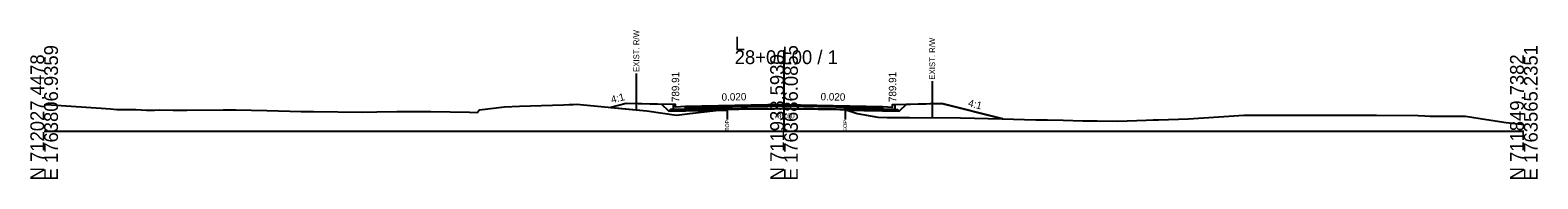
# Model space of a CAD drawing. Extents: x -26 to 5303, y -10 to 9578.
# Drawn here: x 997.2 to 1302.8, y 7990.3 to 8020.5 of the extents above; entities that cross this region are included whole.
import ezdxf

# ---------------------------------------------------------------- set-up
doc = ezdxf.new("R2010")
doc.units = 0
for name, color, linetype in [('Default', 7, 'Continuous'), ('Exist CMT Pavement', 7, 'Continuous'), ('Exist Cross Section Cell', 7, 'Continuous'), ('Exist XS Ground Line', 7, 'Continuous'), ('Old_Level_10', 7, 'Continuous'), ('Old_Level_3', 7, 'Continuous'), ('Prop CMT Conc Surface', 7, 'Continuous'), ('Prop CMT Concrete Structures', 7, 'Continuous'), ('Prop CMT Pvmt Course 1', 7, 'Continuous'), ('Prop CMT Pvmt Course 1 CG', 7, 'Continuous'), ('Prop CMT Pvmt Course 2', 7, 'Continuous'), ('Prop CMT Pvmt Course 3', 7, 'Continuous'), ('Prop CMT Pvmt Surface', 7, 'Continuous'), ('Prop CMT Slope Grass', 7, 'Continuous'), ('Prop CMT Subgrade Earthwork', 7, 'Continuous'), ('Prop XS Earthwork Shape', 7, 'Continuous'), ('Prop XS Hydro Elevations', 7, 'Continuous'), ('Prop XS SE Text', 7, 'Continuous'), ('Prop XS Side Slope Text', 7, 'Continuous'), ('Prop XS Wedging', 7, 'Continuous')]:
    doc.layers.add(name, color=color, linetype=linetype)

msp = doc.modelspace()

# ---------------------------------------------------------------- linework, layer by layer
at = {"layer": 'Exist CMT Pavement'}
msp.add_lwpolyline([(1138.45, 8004.45), (1138.82, 8004.47), (1139.26, 8004.47), (1139.57, 8004.48), (1140.49, 8004.5), (1140.83, 8004.5), (1141.29, 8004.51), (1142.62, 8004.53), (1143.59, 8004.53), (1144.41, 8004.54), (1145.51, 8004.55), (1146.19, 8004.55), (1146.69, 8004.56), (1147.98, 8004.57), (1150.16, 8004.6), (1150.7, 8004.61), (1151.01, 8004.59), (1152.9, 8004.54), (1153.96, 8004.53), (1156, 8004.51), (1156.92, 8004.49), (1158.18, 8004.48), (1159.1, 8004.47), (1160.5, 8004.45), (1161.29, 8004.43), (1161.91, 8004.41), (1162.39, 8004.39)], dxfattribs=at)
at = {"layer": 'Exist Cross Section Cell'}
for p, q in [((1150, 8000), (1150, 8016.43)), ((1000, 8000), (1150, 8000)), ((1150, 8000), (1300, 8000))]:
    msp.add_line(p, q, dxfattribs=at)
at = {"layer": 'Exist XS Ground Line'}
msp.add_lwpolyline([(1000, 8005.43), (1001.45, 8005.38), (1011.56, 8004.68), (1013.42, 8004.52), (1014.73, 8004.39), (1017.08, 8004.4), (1018.58, 8004.4), (1020.74, 8004.3), (1022.39, 8004.3), (1023.47, 8004.31), (1026.15, 8004.3), (1028.91, 8004.3), (1036.31, 8004.33), (1037.84, 8004.33), (1038.86, 8004.34), (1045.13, 8004.18), (1052.11, 8003.98), (1053.17, 8003.99), (1054.62, 8003.97), (1064.52, 8003.88), (1067.48, 8003.91), (1071.51, 8003.97), (1078.41, 8003.97), (1086.26, 8003.89), (1087.76, 8003.82), (1088.26, 8004.32), (1093.36, 8004.93), (1096.35, 8005.05), (1105.26, 8005.33), (1106.44, 8005.39), (1107.24, 8005.43), (1107.9, 8005.48), (1122.18, 8004.12), (1128.22, 8003.26), (1130.88, 8003.62), (1138.45, 8004.45), (1138.82, 8004.47), (1139.26, 8004.47), (1139.57, 8004.48), (1140.49, 8004.5), (1140.83, 8004.5), (1141.29, 8004.51), (1143.59, 8004.53), (1144.41, 8004.54), (1145.51, 8004.55), (1146.19, 8004.55), (1146.69, 8004.56), (1150.16, 8004.6), (1150.7, 8004.61), (1151.01, 8004.59), (1151.56, 8004.56), (1152.9, 8004.54), (1153.35, 8004.54), (1153.96, 8004.53), (1155.13, 8004.52), (1156, 8004.51), (1156.92, 8004.49), (1158.18, 8004.48), (1158.71, 8004.48), (1159.1, 8004.47), (1160.5, 8004.45), (1161.29, 8004.43), (1161.91, 8004.41), (1162.39, 8004.39), (1164.86, 8003.61), (1169, 8002.85), (1170.94, 8002.75), (1175.45, 8002.81), (1185.81, 8002.72), (1194.22, 8002.51), (1201.07, 8002.33), (1203.41, 8002.3), (1206.58, 8002.23), (1210.56, 8002.1), (1213.49, 8002.1), (1217.71, 8002.04), (1223.46, 8002.22), (1224.87, 8002.28), (1225.9, 8002.32), (1232.02, 8002.51), (1239.16, 8002.96), (1243.22, 8003.25), (1244.1, 8003.25), (1245.22, 8003.25), (1270.16, 8003.22), (1278.57, 8003.16), (1279.91, 8003.13), (1281.03, 8003.05), (1288.19, 8003.02), (1292.46, 8002.4), (1296.4, 8001.74), (1299.44, 8001.4), (1300, 8001.34)], dxfattribs=at)
at = {"layer": 'Old_Level_10'}
for p, q in [((1120.05, 8011.72), (1120.05, 8004.32)), ((1180.05, 8010.17), (1180.05, 8002.77)), ((1138.45, 8004.45), (1138.45, 8002.4)), ((1162.39, 8004.39), (1162.39, 8002.34))]:
    msp.add_line(p, q, dxfattribs=at)
at = {"layer": 'Prop CMT Conc Surface'}
for points in [[(1128, 8004.91), (1128, 8005.41), (1127.5, 8005.41)], [(1130, 8005.03), (1128, 8004.91)], [(1170, 8005.03), (1172, 8004.91)], [(1172, 8004.91), (1172, 8005.41), (1172.5, 8005.41)]]:
    msp.add_lwpolyline(points, dxfattribs=at)
at = {"layer": 'Prop CMT Concrete Structures'}
for points in [[(1130, 8005.03), (1128, 8004.91), (1128, 8005.41), (1127.5, 8005.41)], [(1127.5, 8005.41), (1127.5, 8004.4), (1130, 8004.45)], [(1130, 8004.45), (1130, 8005.03)], [(1170, 8005.03), (1172, 8004.91), (1172, 8005.41), (1172.5, 8005.41)], [(1172.5, 8005.41), (1172.5, 8004.4), (1170, 8004.45)], [(1170, 8004.45), (1170, 8005.03)]]:
    msp.add_lwpolyline(points, dxfattribs=at)
at = {"layer": 'Prop CMT Pvmt Course 1'}
for points in [[(1150, 8005.43), (1130, 8005.03)], [(1130, 8005.03), (1130, 8004.78)], [(1130, 8004.78), (1138.45, 8004.95)], [(1138.45, 8004.95), (1150, 8005.18)], [(1138.45, 8004.95), (1138.45, 8004.95)], [(1150, 8005.18), (1150, 8005.43)], [(1150, 8005.43), (1170, 8005.03)], [(1150, 8005.18), (1150, 8005.18), (1150, 8005.18)], [(1162.39, 8004.93), (1150, 8005.18)], [(1170, 8004.78), (1162.39, 8004.93)], [(1162.39, 8004.93), (1162.39, 8004.93)], [(1170, 8005.03), (1170, 8004.78)]]:
    msp.add_lwpolyline(points, dxfattribs=at)
at = {"layer": 'Prop CMT Pvmt Course 1 CG'}
for points in [[(1130, 8004.45), (1127, 8004.39), (1126.66, 8004.04)], [(1126.66, 8004.04), (1130, 8004.11)], [(1130, 8004.11), (1130, 8004.45)], [(1170, 8004.45), (1173, 8004.39), (1173.34, 8004.04)], [(1170, 8004.11), (1170, 8004.45)], [(1173.34, 8004.04), (1170, 8004.11)]]:
    msp.add_lwpolyline(points, dxfattribs=at)
at = {"layer": 'Prop CMT Pvmt Course 2'}
for points in [[(1138.45, 8004.95), (1130, 8004.78)], [(1130, 8004.78), (1130, 8004.45)], [(1130, 8004.45), (1138.45, 8004.61)], [(1138.45, 8004.61), (1138.45, 8004.95)], [(1162.39, 8004.6), (1162.39, 8004.93)], [(1162.39, 8004.93), (1170, 8004.78)], [(1170, 8004.45), (1162.39, 8004.6)], [(1170, 8004.78), (1170, 8004.45)]]:
    msp.add_lwpolyline(points, dxfattribs=at)
at = {"layer": 'Prop CMT Pvmt Course 3'}
for points in [[(1138.45, 8004.61), (1130, 8004.45)], [(1130, 8004.45), (1130, 8004.11)], [(1130, 8004.11), (1138.45, 8004.28)], [(1138.45, 8004.28), (1138.45, 8004.61)], [(1162.39, 8004.6), (1170, 8004.45)], [(1162.39, 8004.26), (1162.39, 8004.6)], [(1170, 8004.11), (1162.39, 8004.26)], [(1170, 8004.45), (1170, 8004.11)]]:
    msp.add_lwpolyline(points, dxfattribs=at)
at = {"layer": 'Prop CMT Pvmt Surface'}
for points in [[(1150, 8005.43), (1130, 8005.03)], [(1150, 8005.43), (1170, 8005.03)]]:
    msp.add_lwpolyline(points, dxfattribs=at)
at = {"layer": 'Prop CMT Slope Grass'}
for points in [[(1127.5, 8005.41), (1118, 8005.6), (1114.87, 8004.82)], [(1172.5, 8005.41), (1182, 8005.6), (1194.37, 8002.51)]]:
    msp.add_lwpolyline(points, dxfattribs=at)
at = {"layer": 'Prop CMT Subgrade Earthwork'}
for p, q in [((1138.45, 8004.45), (1138.45, 8004.28)), ((1162.39, 8004.39), (1162.39, 8004.26))]:
    msp.add_line(p, q, dxfattribs=at)
for points in [[(1130, 8004.11), (1126.66, 8004.04), (1125.25, 8005.45)], [(1138.45, 8004.28), (1130, 8004.11)], [(1162.39, 8004.26), (1170, 8004.11)], [(1170, 8004.11), (1173.34, 8004.04), (1174.75, 8005.45)]]:
    msp.add_lwpolyline(points, dxfattribs=at)
at = {"layer": 'Prop XS Earthwork Shape'}
for points in [[(1122.18, 8004.12), (1128.22, 8003.26), (1130.88, 8003.62), (1136.54, 8004.24), (1130, 8004.11), (1126.66, 8004.04), (1125.25, 8005.45), (1118, 8005.6), (1114.87, 8004.82)], [(1138.45, 8004.45), (1138.45, 8004.28), (1136.54, 8004.24)], [(1162.39, 8004.39), (1162.83, 8004.26), (1162.39, 8004.26)], [(1194.22, 8002.51), (1194.37, 8002.51), (1182, 8005.6), (1174.75, 8005.45), (1173.34, 8004.04), (1170, 8004.11), (1162.83, 8004.26), (1164.86, 8003.61), (1169, 8002.85), (1170.94, 8002.75), (1175.45, 8002.81), (1185.81, 8002.72)]]:
    msp.add_lwpolyline(points, close=True, dxfattribs=at)
at = {"layer": 'Prop XS Wedging'}
for points in [[(1138.45, 8004.45), (1138.45, 8004.95), (1138.83, 8004.95), (1139.26, 8004.96), (1139.57, 8004.97), (1140.49, 8004.99), (1140.83, 8004.99), (1141.29, 8005), (1142.62, 8005.03), (1143.59, 8005.05), (1144.4, 8005.07), (1145.52, 8005.09), (1146.19, 8005.1), (1146.69, 8005.11), (1147.98, 8005.14), (1150, 8005.18), (1150.16, 8005.17), (1150.7, 8005.16), (1151.01, 8005.16), (1152.9, 8005.12), (1153.95, 8005.1), (1156, 8005.06), (1156.92, 8005.04), (1158.18, 8005.01), (1159.11, 8005), (1160.5, 8004.97), (1161.29, 8004.95), (1161.91, 8004.94), (1162.39, 8004.93), (1162.39, 8004.4), (1161.91, 8004.41), (1161.29, 8004.43), (1160.5, 8004.45), (1159.11, 8004.47), (1158.18, 8004.48), (1156.92, 8004.49), (1156, 8004.51), (1153.95, 8004.53), (1152.9, 8004.54), (1151.01, 8004.59), (1150.7, 8004.61), (1150.16, 8004.6), (1150, 8004.6), (1147.98, 8004.57), (1146.69, 8004.56), (1146.19, 8004.55), (1145.52, 8004.55), (1144.4, 8004.54), (1143.59, 8004.53), (1142.62, 8004.53), (1141.29, 8004.51), (1140.83, 8004.5), (1140.49, 8004.5), (1139.57, 8004.48), (1139.26, 8004.47), (1138.83, 8004.47)], [(1152.65, 8004.55), (1152.9, 8004.79), (1152.9, 8004.79), (1152.9, 8004.79), (1153.15, 8004.54), (1152.9, 8004.54)]]:
    msp.add_lwpolyline(points, close=True, dxfattribs=at)

# ---------------------------------------------------------------- texts
at = {"layer": 'Default'}
msp.add_text('-', height=0.0001, dxfattribs=at).set_placement((1000, 8000))
at = {"layer": 'Exist Cross Section Cell'}
for s, p in [('L', (1140, 8016.43)), ('28+00.00 / 1', (1140, 8013.63))]:
    msp.add_text(s, height=2.8, dxfattribs=at).set_placement(p)
for s, p in [('N 712027.4478', (1000, 7990)), ('E 1763806.9359', (1002.8, 7990)), ('N 711938.5930', (1150, 7990)), ('E 1763686.0855', (1152.8, 7990)), ('N 711849.7382', (1300, 7990)), ('E 1763565.2351', (1302.8, 7990))]:
    msp.add_text(s, height=2.8, rotation=90, dxfattribs=at).set_placement(p)
at = {"layer": 'Old_Level_10'}
for s, height, p in [('EXIST. R/W', 1.181, (1120.64, 8012.03)), ('EXIST. R/W', 1.181, (1180.64, 8010.47)), ('EOP', 0.787, (1138.85, 8000.01)), ('EOP', 0.787, (1162.79, 7999.95))]:
    msp.add_text(s, height=height, rotation=90, dxfattribs=at).set_placement(p)
at = {"layer": 'Old_Level_3'}
msp.add_text('789.60', height=1, dxfattribs=at).set_placement((1147.95, 8002.6))
at = {"layer": 'Prop XS Hydro Elevations'}
for p in [(1128.75, 8005.91), (1172.75, 8005.91)]:
    msp.add_text('789.91', height=1.5, rotation=90, dxfattribs=at).set_placement(p)
at = {"layer": 'Prop XS SE Text'}
for rotation, p in [(1.1458, (1137.36, 8006.18)), (358.8542, (1157.4, 8006.28))]:
    msp.add_text('0.020', height=1.5, rotation=rotation, dxfattribs=at).set_placement(p)
at = {"layer": 'Prop XS Side Slope Text'}
for rotation, p in [(14.0362, (1115.1, 8005.65)), (345.9638, (1187.21, 8005.07))]:
    msp.add_text('4:1', height=1.5, rotation=rotation, dxfattribs=at).set_placement(p)

doc.saveas('drawing.dxf')
